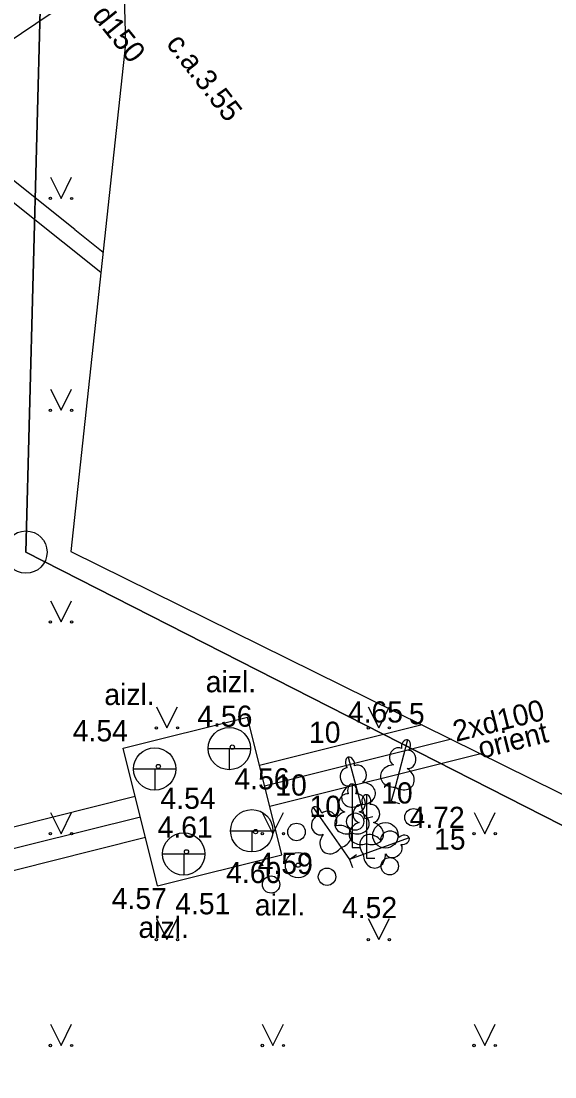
# Model space of a CAD drawing. Extents: x 519536 to 519949, y 326041 to 326519.
# Drawn here: x 519634.06 to 519646.66, y 326334.26 to 326359.19 of the extents above; entities that cross this region are included whole.
import ezdxf

# ---------------------------------------------------------------- set-up
doc = ezdxf.new("R2010")
doc.units = 0
for name, color, linetype in [('APGR_ELEM_####_####_#', 7, 'Continuous'), ('APGR_SARK_####_####_#', 7, 'Continuous'), ('RAMI_UZMR_####_####_#', 7, 'Continuous'), ('RELJ_AATZ_####_TKST_#', 7, 'Continuous'), ('RELJ_ELEM_####_####_#', 7, 'Continuous'), ('ROBZ_UZMR_####_####_#', 7, 'Continuous'), ('SILT_ELEM_####_####_#', 7, 'Continuous'), ('SILT_ELEM_####_TKST_#', 7, 'Continuous'), ('SILT_VADP_NEDR_####_#', 7, 'Continuous'), ('SILT_VADP_NEDR_TKST_#', 7, 'Continuous'), ('SILT_VADP_UDEN_KONT_#', 7, 'Continuous'), ('SKAN_VADP_SPDK_####_#', 7, 'Continuous'), ('TERT_DIAM_####_TKST_#', 7, 'Continuous'), ('TERT_ELEM_####_####_#', 7, 'Continuous'), ('UDTK_VADP_NEDR_####_#', 7, 'Continuous'), ('UDTK_VADP_UDEN_TKST_#', 7, 'Continuous')]:
    doc.layers.add(name, color=color, linetype=linetype)

msp = doc.modelspace()

# ---------------------------------------------------------------- linework, layer by layer
at = {"layer": 'APGR_ELEM_####_####_#'}
msp.add_circle((519634.17, 326346.65), 0.5, dxfattribs=at)
at = {"layer": 'APGR_SARK_####_####_#'}
for p, q in [((519634.774, 326369.546), (519634.167, 326346.646)), ((519634.167, 326346.646), (519658.484, 326334.259))]:
    msp.add_line(p, q, dxfattribs=at)
at = {"layer": 'RAMI_UZMR_####_####_#'}
msp.add_lwpolyline([(519636.229, 326369.014), (519636.521, 326358.648), (519635.235, 326346.665), (519658.236, 326335.303), (519677.714, 326342.785), (519698.5, 326350)], dxfattribs=at)
at = {"layer": 'RELJ_ELEM_####_####_#'}
for centre in [(519639.043, 326342.047), (519637.297, 326341.588), (519639.591, 326340.051), (519637.961, 326339.573), (519640.596, 326339.258)]:
    msp.add_circle(centre, 0.05, dxfattribs=at)
at = {"layer": 'ROBZ_UZMR_####_####_#'}
for p, q in [((519634.167, 326346.646), (519634.774, 326369.546)), ((519658.484, 326334.259), (519634.167, 326346.646))]:
    msp.add_line(p, q, dxfattribs=at)
at = {"layer": 'SILT_ELEM_####_####_#'}
for p, q in [((519638.472, 326342.012), (519638.972, 326342.012)), ((519638.972, 326342.012), (519639.472, 326342.012)), ((519638.972, 326342.012), (519638.972, 326341.512)), ((519636.711, 326341.53), (519637.211, 326341.53)), ((519637.211, 326341.53), (519637.711, 326341.53)), ((519637.211, 326341.53), (519637.211, 326341.03)), ((519639.003, 326340.069), (519639.503, 326340.069)), ((519639.503, 326340.069), (519640.003, 326340.069)), ((519639.503, 326340.069), (519639.503, 326339.569)), ((519637.395, 326339.522), (519637.895, 326339.522)), ((519637.895, 326339.522), (519638.395, 326339.522)), ((519637.895, 326339.522), (519637.895, 326339.022))]:
    msp.add_line(p, q, dxfattribs=at)
for centre in [(519638.972, 326342.012), (519637.211, 326341.53), (519639.503, 326340.069), (519637.895, 326339.522)]:
    msp.add_circle(centre, 0.5, dxfattribs=at)
at = {"layer": 'SILT_VADP_NEDR_####_#'}
for p, q in [((519643.869, 326342.144), (519639.806, 326341.127)), ((519644.213, 326342.23), (519643.869, 326342.144)), ((519636.872, 326340.393), (519634.277, 326339.744)), ((519634.277, 326339.744), (519627.467, 326338.04))]:
    msp.add_line(p, q, dxfattribs=at)
at = {"layer": 'SILT_VADP_UDEN_KONT_#'}
for p, q in [((519636.465, 326342.019), (519639.4, 326342.753)), ((519640.213, 326339.501), (519639.4, 326342.753)), ((519643.521, 326342.572), (519639.685, 326341.612)), ((519637.279, 326338.767), (519636.465, 326342.019)), ((519644.907, 326341.888), (519639.928, 326340.642)), ((519636.751, 326340.878), (519633.843, 326340.151)), ((519636.993, 326339.908), (519634.712, 326339.337)), ((519637.279, 326338.767), (519640.213, 326339.501)), ((519634.712, 326339.337), (519627.524, 326337.539))]:
    msp.add_line(p, q, dxfattribs=at)
at = {"layer": 'SKAN_VADP_SPDK_####_#'}
for points in [[(519635.325, 326354.267), (519614.148, 326371.204), (519578.028, 326400.094)], [(519578.247, 326399.405), (519614.012, 326370.8), (519635.045, 326353.978)], [(519635.325, 326354.267), (519635.993, 326353.732)], [(519635.045, 326353.978), (519635.943, 326353.26)]]:
    msp.add_lwpolyline(points, dxfattribs=at)
at = {"layer": 'TERT_ELEM_####_####_#'}
for p, q in [((519634.75, 326355.5), (519635, 326355)), ((519635, 326355), (519635.25, 326355.5)), ((519634.75, 326350.5), (519635, 326350)), ((519635, 326350), (519635.25, 326350.5)), ((519634.75, 326345.5), (519635, 326345)), ((519635, 326345), (519635.25, 326345.5)), ((519637.25, 326343), (519637.5, 326342.5)), ((519637.5, 326342.5), (519637.75, 326343)), ((519642.25, 326343), (519642.5, 326342.5)), ((519642.5, 326342.5), (519642.75, 326343)), ((519642.883, 326341.103), (519642.793, 326340.768)), ((519642.079, 326340.693), (519642.169, 326340.358)), ((519642.793, 326340.768), (519642.986, 326340.716)), ((519634.75, 326340.5), (519635, 326340)), ((519635, 326340), (519635.25, 326340.5)), ((519639.75, 326340.5), (519640, 326340)), ((519640, 326340), (519640.25, 326340.5)), ((519642.169, 326340.358), (519642.362, 326340.41)), ((519644.75, 326340.5), (519645, 326340)), ((519645, 326340), (519645.25, 326340.5)), ((519641.869, 326340.02), (519641.869, 326339.673)), ((519641.61, 326339.677), (519641.809, 326339.393)), ((519641.869, 326339.673), (519642.069, 326339.673)), ((519642.207, 326339.769), (519642.207, 326339.422)), ((519642.135, 326339.512), (519641.809, 326339.393)), ((519641.809, 326339.393), (519641.973, 326339.508)), ((519641.809, 326339.393), (519641.877, 326339.205)), ((519642.207, 326339.422), (519642.407, 326339.422)), ((519637.25, 326338), (519637.5, 326337.5)), ((519637.5, 326337.5), (519637.75, 326338)), ((519642.25, 326338), (519642.5, 326337.5)), ((519642.5, 326337.5), (519642.75, 326338)), ((519634.75, 326335.5), (519635, 326335)), ((519635, 326335), (519635.25, 326335.5)), ((519639.75, 326335.5), (519640, 326335)), ((519640, 326335), (519640.25, 326335.5)), ((519644.75, 326335.5), (519645, 326335)), ((519645, 326335), (519645.25, 326335.5))]:
    msp.add_line(p, q, dxfattribs=at)
for points in [[(519643.181, 326342.217), (519642.883, 326341.103)], [(519643.208, 326341.969), (519643.207, 326341.97)], [(519641.781, 326341.807), (519642.079, 326340.693)], [(519641.927, 326341.606), (519641.926, 326341.606)], [(519641.869, 326341.173), (519641.869, 326340.02)], [(519641.959, 326340.941), (519641.958, 326340.942)], [(519642.207, 326340.922), (519642.207, 326339.769)], [(519640.949, 326340.622), (519641.61, 326339.677)], [(519642.297, 326340.69), (519642.296, 326340.691)], [(519641.155, 326340.483), (519641.154, 326340.483)], [(519643.219, 326339.906), (519642.135, 326339.512)], [(519643.031, 326339.742), (519643.031, 326339.744)]]:
    msp.add_lwpolyline(points, dxfattribs=at)
for centre, radius in [((519634.75, 326355), 0.028), ((519635.25, 326355), 0.0263), ((519634.75, 326350), 0.028), ((519635.25, 326350), 0.0263), ((519634.75, 326345), 0.028), ((519635.25, 326345), 0.0263), ((519637.25, 326342.5), 0.028), ((519637.75, 326342.5), 0.0263), ((519642.25, 326342.5), 0.028), ((519642.75, 326342.5), 0.0263), ((519643.318, 326340.387), 0.207), ((519641.943, 326340.286), 0.204), ((519640.559, 326340.043), 0.207), ((519642.657, 326339.962), 0.301), ((519634.75, 326340), 0.028), ((519635.25, 326340), 0.0263), ((519639.75, 326340), 0.028), ((519640.25, 326340), 0.0263), ((519644.75, 326340), 0.028), ((519645.25, 326340), 0.0263), ((519640.596, 326339.258), 0.301), ((519642.76, 326339.234), 0.205), ((519641.278, 326338.984), 0.205), ((519639.958, 326338.801), 0.204), ((519637.25, 326337.5), 0.028), ((519637.75, 326337.5), 0.0263), ((519642.25, 326337.5), 0.028), ((519642.75, 326337.5), 0.0263), ((519634.75, 326335), 0.028), ((519635.25, 326335), 0.0263), ((519639.75, 326335), 0.028), ((519640.25, 326335), 0.0263), ((519644.75, 326335), 0.028), ((519645.25, 326335), 0.0263)]:
    msp.add_circle(centre, radius, dxfattribs=at)
for centre, major_axis, ratio, start_param, end_param in [((519643.143, 326342.072), (-0.039, -0.145), 0.707107, 3.14537, 5.287485), ((519643.142, 326342.072), (-0.039, -0.145), 0.707107, 0.995701, 3.137816), ((519642.942, 326341.82), (-0.092, -0.195), 0.861323, 3.141593, 6.283185), ((519643.19, 326341.754), (-0.018, -0.215), 0.861323, 6.283185, 9.424778), ((519641.82, 326341.662), (0.039, -0.145), 0.707107, 3.14537, 5.287485), ((519641.819, 326341.662), (0.039, -0.145), 0.707107, 0.995701, 3.137816), ((519642.02, 326341.41), (0.092, -0.195), 0.861323, 6.283185, 9.424778), ((519642.86, 326341.364), (0.321, 0.012), 0.814445, 1.570796, 4.752015), ((519641.772, 326341.344), (0.018, -0.215), 0.861323, 3.141593, 6.283185), ((519643.033, 326341.318), (-0.272, 0.171), 0.814445, 1.531171, 4.712389), ((519641.929, 326340.908), (0.272, 0.171), 0.814445, 1.570796, 4.752015), ((519641.869, 326341.023), (0, -0.15), 0.707107, 3.14537, 5.287485), ((519641.869, 326341.023), (0, -0.15), 0.707107, 0.995701, 3.137816), ((519642.102, 326340.954), (-0.321, 0.012), 0.814445, 1.531171, 4.712389), ((519641.741, 326340.728), (-0.039, -0.212), 0.861323, 3.141593, 6.283185), ((519641.997, 326340.728), (0.039, -0.212), 0.861323, 0, 3.141593), ((519642.207, 326340.772), (0, -0.15), 0.707107, 3.14537, 5.287485), ((519642.207, 326340.772), (0, -0.15), 0.707107, 0.995701, 3.137816), ((519641.035, 326340.499), (0.086, -0.123), 0.707107, 3.14537, 5.287485), ((519641.034, 326340.499), (0.086, -0.123), 0.707107, 0.995701, 3.137816), ((519642.079, 326340.477), (-0.039, -0.212), 0.861323, 3.141593, 6.283185), ((519642.335, 326340.477), (0.039, -0.212), 0.861323, 0, 3.141593), ((519641.099, 326340.184), (0.09, -0.196), 0.861323, 3.141593, 6.283185), ((519641.309, 326340.331), (0.154, -0.152), 0.861323, 0, 3.141593), ((519641.779, 326340.266), (0.307, 0.095), 0.814445, 1.570796, 4.752015), ((519641.959, 326340.266), (-0.307, 0.095), 0.814445, 1.531171, 4.712389), ((519641.542, 326339.93), (-0.306, -0.098), 0.814445, 1.531171, 4.712389), ((519642.117, 326340.015), (0.307, 0.095), 0.814445, 1.570796, 4.752015), ((519642.297, 326340.015), (-0.307, 0.095), 0.814445, 1.531171, 4.712389), ((519641.396, 326339.827), (0.197, 0.254), 0.814445, 1.570796, 4.752015), ((519642.336, 326339.68), (0.194, -0.256), 0.814445, 1.570796, 4.752015), ((519642.757, 326339.874), (-0.213, -0.036), 0.861323, 3.141593, 6.283185), ((519643.078, 326339.854), (-0.141, -0.051), 0.707107, 3.14537, 5.287485), ((519643.078, 326339.855), (-0.141, -0.051), 0.707107, 0.995701, 3.137816), ((519642.844, 326339.633), (-0.186, -0.109), 0.861323, 0, 3.141593), ((519642.397, 326339.512), (-0.016, 0.321), 0.814445, 1.531171, 4.712389)]:
    msp.add_ellipse(centre, major_axis=major_axis, ratio=ratio, start_param=start_param, end_param=end_param, dxfattribs=at)
at = {"layer": 'UDTK_VADP_NEDR_####_#'}
msp.add_lwpolyline([(519606.267, 326338.715), (519622.4, 326351.044), (519635.833, 326360.1)], dxfattribs=at)

# ---------------------------------------------------------------- texts
at = {"layer": 'RELJ_AATZ_####_TKST_#'}
for s, p in [('4.65', (519641.77, 326342.626)), ('4.56', (519639.093, 326341.047)), ('4.54', (519637.347, 326340.588)), ('4.72', (519643.226, 326340.137)), ('4.61', (519637.279, 326339.908)), ('4.59', (519639.641, 326339.051)), ('4.51', (519637.695, 326338.097)), (' 4.52', (519641.445, 326338.007))]:
    msp.add_text(s, height=0.5, dxfattribs=at).set_placement(p)
at = {"layer": 'SILT_ELEM_####_TKST_#'}
for s, p in [('aizl.', (519638.415, 326343.341)), ('aizl.', (519636.022, 326343.039)), (' 4.56', (519638.031, 326342.526)), (' 4.54', (519635.091, 326342.182)), (' 4.60', (519638.711, 326338.835)), (' 4.57', (519636.011, 326338.222)), ('aizl.', (519639.575, 326338.07)), ('aizl.', (519636.828, 326337.541))]:
    msp.add_text(s, height=0.5, dxfattribs=at).set_placement(p)
at = {"layer": 'SILT_VADP_NEDR_TKST_#'}
for s, p in [('2xd100', (519644.321, 326342.165)), ('orient', (519644.914, 326341.767))]:
    msp.add_text(s, height=0.5, rotation=14.0449, dxfattribs=at).set_placement(p)
at = {"layer": 'TERT_DIAM_####_TKST_#'}
for s, p in [(' 5', (519643.025, 326342.585)), ('10', (519640.853, 326342.146)), ('10', (519640.057, 326340.901)), ('10', (519642.556, 326340.714)), ('10', (519640.865, 326340.398)), ('15', (519643.805, 326339.623))]:
    msp.add_text(s, height=0.5, dxfattribs=at).set_placement(p)
at = {"layer": 'UDTK_VADP_UDEN_TKST_#'}
for s, rotation, p in [('d150', 308.8073, (519635.71, 326359.318)), ('c.a.3.55', 307.8222, (519637.462, 326358.649))]:
    msp.add_text(s, height=0.5, rotation=rotation, dxfattribs=at).set_placement(p)

doc.saveas('drawing.dxf')
